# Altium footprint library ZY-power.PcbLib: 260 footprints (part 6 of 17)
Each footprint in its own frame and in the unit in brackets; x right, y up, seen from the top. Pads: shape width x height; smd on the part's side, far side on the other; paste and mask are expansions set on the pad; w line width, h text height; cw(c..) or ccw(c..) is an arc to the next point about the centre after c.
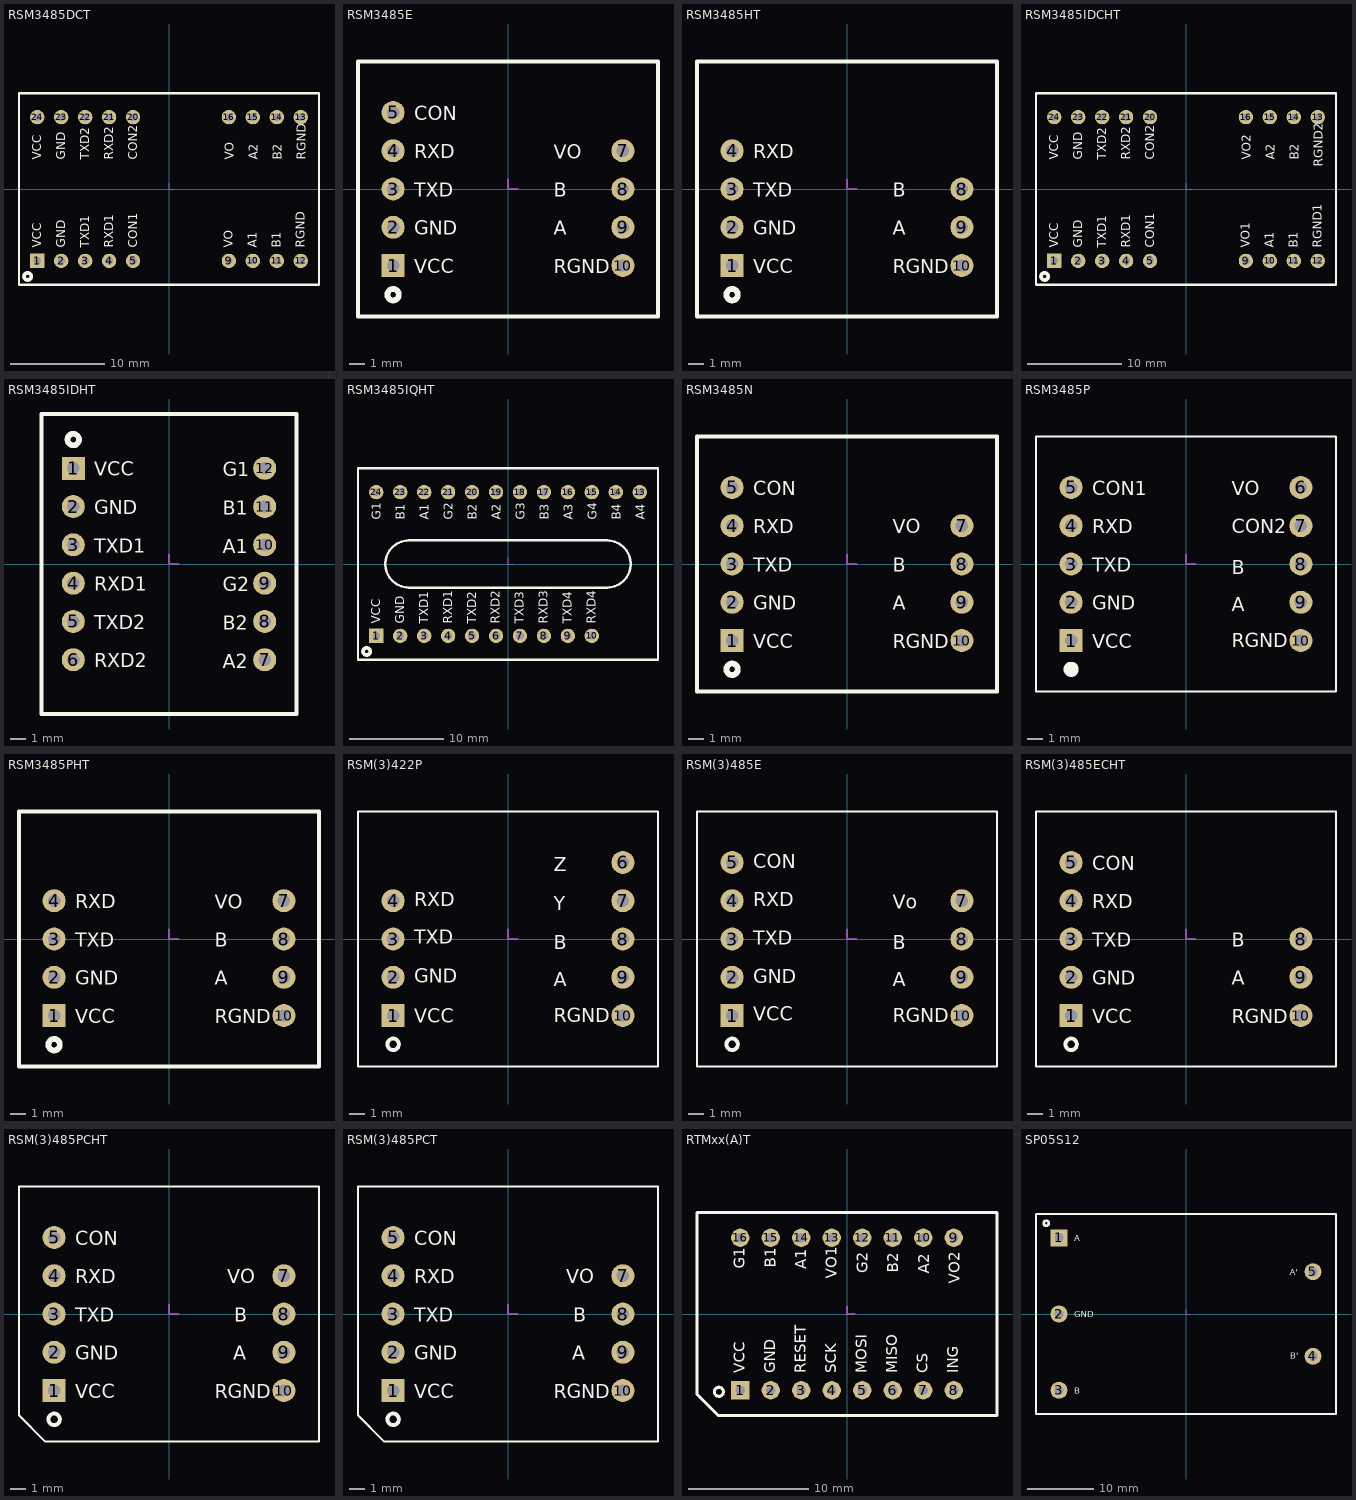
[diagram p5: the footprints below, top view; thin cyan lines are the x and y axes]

## RSM3485DCT [mil]
height 374.02
pads (18):
  rect 60x60 hole 32: 1(-550,-300)
  round 60 hole 32: 2(-450,-300) 3(-350,-300) 4(-250,-300) 5(-150,-300) 9(250,-300) 10(350,-300) 11(450,-300) 12(550,-300) 13(550,300) 14(450,300) 15(350,300) 16(250,300) 20(-150,300) 21(-250,300) 22(-350,300) 23(-450,300) 24(-550,300)
Top Overlay:
  circle w15: c-590,-365 r15
  lines w10: -625.98,-399.61 625.98,-399.61 625.98,399.61 -625.98,399.61 -625.98,-399.61
  text "VCC" at -533,-245 h36
  text "GND" at -433,-245 h36
  text "TXD1" at -333,-245 h36
  text "RXD1" at -233,-245 h36
  text "CON1" at -133,-245 h36
  text "VO" at 267,-245 h36
  text "A1" at 367,-245 h36
  text "B1" at 467,-245 h36
  text "RGND" at 567,-245 h36
  text "RGND" at 570,123 h36
  text "B2" at 469.73,123 h36
  text "A2" at 369.45,123 h36
  text "VO" at 269.18,123 h36
  text "VCC" at -533,123 h36
  text "GND" at -432.73,123 h36
  text "TXD2" at -332.45,123 h36
  text "CON2" at -131.91,123 h36
  text "RXD2" at -232.18,123 h36
Mechanical 15:
  lines w5: 0,25 0,0 25,0

## RSM3485E [mil]
height 277.56
pads (9):
  rect 60x60 hole 32: 1(-300,-200)
  round 60 hole 32: 2(-300,-100) 3(-300,0) 4(-300,100) 5(-300,200) 7(300,100) 8(300,0) 9(300,-100) 10(300,-200)
Top Overlay:
  circle w15: c-300,-276 r15
  lines w10: -391.73,-332.68 -391.73,332.68 391.73,332.68 391.73,-332.68 -391.73,-332.68
  text "VCC" at -245,-220 h36
  text "GND" at -245,-120 h36
  text "RXD" at -245,80 h36
  text "TXD" at -245,-20 h36
  text "RGND" at 120,-220 h36
  text "B" at 120,-20 h36
  text "A" at 120,-120 h36
  text "VO" at 120,79 h36
  text "CON" at -245,180 h36
Mechanical 15:
  lines w5: 0,25 0,0 25,0

## RSM3485HT [mil]
height 277.56
pads (7):
  rect 60x60 hole 32: 1(-300,-200)
  round 60 hole 32: 2(-300,-100) 3(-300,0) 4(-300,100) 8(300,0) 9(300,-100) 10(300,-200)
Top Overlay:
  circle w15: c-300,-276 r15
  lines w10: -391.73,-332.68 -391.73,332.68 391.73,332.68 391.73,-332.68 -391.73,-332.68
  text "VCC" at -245,-220 h36
  text "GND" at -245,-120 h36
  text "RXD" at -245,80 h36
  text "TXD" at -245,-20 h36
  text "RGND" at 120,-220 h36
  text "B" at 120,-20 h36
  text "A" at 120,-120 h36
Mechanical 15:
  lines w5: 0,25 0,0 25,0

## RSM3485IDCHT [mil]
height 255.91
pads (18):
  rect 60x60 hole 32: 1(-550,-300)
  round 60 hole 32: 2(-450,-300) 3(-350,-300) 4(-250,-300) 5(-150,-300) 9(250,-300) 10(350,-300) 11(450,-300) 12(550,-300) 13(550,300) 14(450,300) 15(350,300) 16(250,300) 20(-150,300) 21(-250,300) 22(-350,300) 23(-450,300) 24(-550,300)
Top Overlay:
  circle w15: c-590,-365 r15
  lines w10: -625.98,-399.61 -625.98,399.61 625.98,399.61 625.98,-399.61 -625.98,-399.61
  text "RXD2" at -232.18,123 h36
  text "CON2" at -131.91,123 h36
  text "TXD2" at -332.45,123 h36
  text "GND" at -432.73,123 h36
  text "VCC" at -533,123 h36
  text "VO2" at 269.18,123 h36
  text "A2" at 369.45,123 h36
  text "B2" at 469.73,123 h36
  text "RGND2" at 570,92 h36
  text "RGND1" at 567,-245 h36
  text "B1" at 467,-245 h36
  text "A1" at 367,-245 h36
  text "VO1" at 267,-245 h36
  text "CON1" at -133,-245 h36
  text "RXD1" at -233,-245 h36
  text "TXD1" at -333,-245 h36
  text "GND" at -433,-245 h36
  text "VCC" at -533,-245 h36
Mechanical 15:
  lines w5: 0,25 0,0 25,0

## RSM3485IDHT [mil]
height 277.56
pads (12):
  rect 60x60 hole 32: 1(-250,250)
  round 60 hole 32: 2(-250,150) 3(-250,50) 4(-250,-50) 5(-250,-150) 6(-250,-250) 7(250,-250) 8(250,-150) 9(250,-50) 10(250,50) 11(250,150) 12(250,250)
Top Overlay:
  circle w15: c-250,325 r15
  lines w10: -332.68,-391.73 332.68,-391.73 332.68,391.73 -332.68,391.73 -332.68,-391.73
  text "G1" at 140.69,229 h36
  text "G2" at 140.69,-71.6 h36
  text "A1" at 140.69,28.6 h36
  text "B1" at 140.69,128.8 h36
  text "VCC" at -195,230 h36
  text "GND" at -195,130 h36
  text "TXD1" at -195,30 h36
  text "RXD1" at -195,-70 h36
  text "B2" at 140.69,-171.8 h36
  text "A2" at 140.69,-272 h36
  text "RXD2" at -195,-270 h36
  text "TXD2" at -195,-170 h36
Mechanical 15:
  lines w5: 0,25 0,0 25,0

## RSM3485IQHT [mil]
height 374.02
pads (22):
  rect 60x60 hole 32: 1(-550,-300)
  round 60 hole 32: 2(-450,-300) 3(-350,-300) 4(-250,-300) 5(-150,-300) 6(-50,-300) 7(50,-300) 8(150,-300) 9(250,-300) 10(350,-300) 13(550,300) 14(450,300) 15(350,300) 16(250,300) 17(150,300) 18(50,300) 19(-50,300) 20(-150,300) 21(-250,300) 22(-350,300) 23(-450,300) 24(-550,300)
Top Overlay:
  circle w15: c-590,-365 r15
  lines w10: -625.98,-399.61 625.98,-399.61 625.98,399.61 -625.98,399.61 -625.98,-399.61 ; -413.39,-98.43 cw(c-413.39,0) -413.39,98.43 413.39,98.43 cw(c413.39,0) 413.39,-98.43 -413.39,-98.43
  text "VCC" at -533,-249 h36
  text "GND" at -433.11,-249 h36
  text "TXD1" at -333.22,-249 h36
  text "RXD1" at -233.33,-249 h36
  text "TXD2" at -133.44,-249 h36
  text "A4" at 570,185 h36
  text "B4" at 469.82,185 h36
  text "G4" at 369.64,185 h36
  text "A3" at 269.45,185 h36
  text "G1" at -532,185 h36
  text "B1" at -431.82,185 h36
  text "A1" at -331.64,185 h36
  text "B2" at -131.27,185 h36
  text "G2" at -231.45,185 h36
  text "RXD2" at -33.56,-249 h36
  text "TXD3" at 66.33,-249 h36
  text "RXD3" at 166.22,-249 h36
  text "TXD4" at 266.11,-249 h36
  text "RXD4" at 366,-249 h36
  text "B3" at 169.27,185 h36
  text "G3" at 69.09,185 h36
  text "A2" at -31.09,185 h36
Mechanical 15:
  lines w5: 0,25 0,0 25,0

## RSM3485N [mil]
height 277.56
pads (9):
  rect 60x60 hole 32: 1(-300,-200)
  round 60 hole 32: 2(-300,-100) 3(-300,0) 4(-300,100) 5(-300,200) 7(300,100) 8(300,0) 9(300,-100) 10(300,-200)
Top Overlay:
  circle w15: c-300,-275 r15
  lines w10: -391.73,-332.68 391.73,-332.68 391.73,332.68 -391.73,332.68 -391.73,-332.68
  text "A" at 120,-120 h36
  text "B" at 120,-20 h36
  text "RGND" at 120,-220 h36
  text "TXD" at -245,-20 h36
  text "RXD" at -245,80 h36
  text "GND" at -245,-120 h36
  text "CON" at -245,180 h36
  text "VCC" at -245,-220 h36
  text "VO" at 120,80 h36
Mechanical 15:
  lines w5: 0,25 0,0 25,0

## RSM3485P [mil]
height 277.56
pads (10):
  rect 60x60 hole 32: 1(-300,-200)
  round 60 hole 32: 2(-300,-100) 3(-300,0) 4(-300,100) 5(-300,200) 6(300,200) 7(300,100) 8(300,0) 9(300,-100) 10(300,-200)
Top Overlay:
  circle w19.68: c-300,-275 r9.84
  lines w5: -391.73,-332.68 -391.73,332.68 391.73,332.68 391.73,-332.68 -391.73,-332.68
  text "RGND" at 120,-218 h36
  text "A" at 120,-123 h36
  text "B" at 120,-27 h36
  text "CON1" at -245,180 h36
  text "RXD" at -245,80 h36
  text "TXD" at -245,-20 h36
  text "GND" at -245,-119 h36
  text "VCC" at -245,-220 h36
  text "CON2" at 120,80 h36
  text "VO" at 120,180 h36
Mechanical 15:
  lines w5: 0,25 0,0 25,0

## RSM3485PHT [mil]
height 277.56
pads (8):
  rect 60x60 hole 32: 1(-300,-200)
  round 60 hole 32: 2(-300,-100) 3(-300,0) 4(-300,100) 7(300,100) 8(300,0) 9(300,-100) 10(300,-200)
Top Overlay:
  circle w15: c-300,-276 r15
  lines w10: -391.73,-332.68 391.73,-332.68 391.73,332.68 -391.73,332.68 -391.73,-332.68
  text "VO" at 120,79 h36
  text "A" at 120,-120 h36
  text "B" at 120,-20 h36
  text "RGND" at 120,-220 h36
  text "TXD" at -245,-20 h36
  text "RXD" at -245,80 h36
  text "GND" at -245,-120 h36
  text "VCC" at -245,-220 h36
Mechanical 15:
  lines w5: 0,25 0,0 25,0

## RSM(3)422P [mil]
height 277.56
pads (9):
  rect 60x60 hole 32: 1(-300,-200)
  round 60 hole 32: 2(-300,-100) 3(-300,0) 4(-300,100) 6(300,200) 7(300,100) 8(300,0) 9(300,-100) 10(300,-200)
Top Overlay:
  circle w10: c-300,-275 r15
  lines w5: -391.73,-332.68 -391.73,332.68 391.73,332.68 391.73,-332.68 -391.73,-332.68
  text "RGND" at 120,-218 h36
  text "A" at 120,-123 h36
  text "B" at 120,-27 h36
  text "Y" at 120,75 h36
  text "Z" at 120,177 h36
  text "RXD" at -245,85 h36
  text "TXD" at -245,-13 h36
  text "GND" at -245,-114 h36
  text "VCC" at -245,-219 h36
Mechanical 15:
  lines w5: 0,25 0,0 25,0

## RSM(3)485E [mil]
height 277.56
pads (9):
  rect 60x60 hole 32: 1(-300,-200)
  round 60 hole 32: 2(-300,-100) 3(-300,0) 4(-300,100) 5(-300,200) 7(300,100) 8(300,0) 9(300,-100) 10(300,-200)
Top Overlay:
  circle w10: c-300,-275 r15
  lines w5: -391.73,-332.68 391.73,-332.68 391.73,332.68 -391.73,332.68 -391.73,-332.68
  text "VCC" at -245,-214 h36
  text "GND" at -245,-115 h36
  text "TXD" at -245,-15 h36
  text "RXD" at -245,85 h36
  text "CON" at -245,185 h36
  text "Vo" at 120,79 h36
  text "B" at 120,-27 h36
  text "A" at 120,-123 h36
  text "RGND" at 120,-218 h36
Mechanical 15:
  lines w5: 0,25 0,0 25,0

## RSM(3)485ECHT [mil]
height 277.56
pads (8):
  rect 60x60 hole 32: 1(-300,-200)
  round 60 hole 32: 2(-300,-100) 3(-300,0) 4(-300,100) 5(-300,200) 8(300,0) 9(300,-100) 10(300,-200)
Top Overlay:
  circle w10: c-300,-275 r15
  lines w5: -391.73,-332.68 391.73,-332.68 391.73,332.68 -391.73,332.68 -391.73,-332.68
  text "A" at 120,-120 h36
  text "B" at 120,-20 h36
  text "RGND" at 120,-220 h36
  text "TXD" at -245,-20 h36
  text "RXD" at -245,80 h36
  text "GND" at -245,-120 h36
  text "CON" at -245,180 h36
  text "VCC" at -245,-220 h36
Mechanical 15:
  lines w5: 0,25 0,0 25,0

## RSM(3)485PCHT [mil]
height 277.56
pads (9):
  rect 60x60 hole 32: 1(-300,-200)
  round 60 hole 32: 2(-300,-100) 3(-300,0) 4(-300,100) 5(-300,200) 7(300,100) 8(300,0) 9(300,-100) 10(300,-200)
Top Overlay:
  circle w10: c-300,-275 r15
  lines w5: -391.73,-265 -391.73,332.68 391.73,332.68 391.73,-332.68 -324.06,-332.68 -391.73,-265
  text "A" at 168.25,-120 h36
  text "B" at 169.96,-20 h36
  text "RGND" at 120,-220 h36
  text "TXD" at -245,-20 h36
  text "RXD" at -245,80 h36
  text "GND" at -245,-120 h36
  text "CON" at -245,180 h36
  text "VCC" at -245,-220 h36
  text "VO" at 152.22,80 h36
Mechanical 15:
  lines w5: 0,25 0,0 25,0

## RSM(3)485PCT [mil]
height 277.56
pads (9):
  rect 60x60 hole 32: 1(-300,-200)
  round 60 hole 32: 2(-300,-100) 3(-300,0) 4(-300,100) 5(-300,200) 7(300,100) 8(300,0) 9(300,-100) 10(300,-200)
Top Overlay:
  circle w10: c-300,-275 r15
  lines w5: -391.73,-265 -324.06,-332.68 391.73,-332.68 391.73,332.68 -391.73,332.68 -391.73,-265
  text "VO" at 152.22,80 h36
  text "VCC" at -245,-220 h36
  text "CON" at -245,180 h36
  text "GND" at -245,-120 h36
  text "RXD" at -245,80 h36
  text "TXD" at -245,-20 h36
  text "RGND" at 120,-220 h36
  text "B" at 169.96,-20 h36
  text "A" at 168.25,-120 h36
Mechanical 15:
  lines w5: 0,25 0,0 25,0

## RTMxx(A)T [mil]
height 279.53
pads (16):
  rect 60x60 hole 32: 1(-350,-250)
  round 60 hole 32: 2(-250,-250) 3(-150,-250) 4(-50,-250) 5(50,-250) 6(150,-250) 7(250,-250) 8(350,-250) 9(350,250) 10(250,250) 11(150,250) 12(50,250) 13(-50,250) 14(-150,250) 15(-250,250) 16(-350,250)
Top Overlay:
  circle w10: c-420,-255 r15
  lines w10: -491.73,-263.27 -422.32,-332.68 491.73,-332.68 491.73,332.68 -491.73,332.68 -491.73,-263.27
  text "G1" at -335,149.03 h36
  text "B1" at -234.29,150.92 h36
  text "A1" at -133.57,147.15 h36
  text "VO1" at -32.86,115.1 h36
  text "G2" at 67.86,133.61 h36
  text "B2" at 168.57,135.5 h36
  text "MISO" at 165,-195 h36
  text "MOSI" at 65,-195 h36
  text "SCK" at -35,-195 h36
  text "RESET" at -135,-195 h36
  text "GND" at -235,-195 h36
  text "A2" at 269.29,131.72 h36
  text "VCC" at -335,-195 h36
  text "CS" at 265,-195 h36
  text "ING" at 365,-195 h36
  text "VO2" at 370,99.67 h36
Mechanical 15:
  lines w5: 0,25 0,0 25,0

## SP05S12 [mil]
height 834.65
pads (5):
  rect 100x100 hole 55: 1(-750,450)
  round 100 hole 55: 2(-750,0) 3(-750,-450) 4(750,-250) 5(750,250)
Top Overlay:
  circle w15: c-825,536 r15
  lines w10: -885.83,-590.55 -885.83,590.55 885.83,590.55 885.83,-590.55 -885.83,-590.55
  text "B" at -660,-470 h36
  text "A" at -660,431 h36
  text "GND" at -660,-19.5 h36
  text "A'" at 612.23,230 h36
  text "B'" at 616,-265 h36
Mechanical 15:
  lines w5: 0,25 0,0 25,0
